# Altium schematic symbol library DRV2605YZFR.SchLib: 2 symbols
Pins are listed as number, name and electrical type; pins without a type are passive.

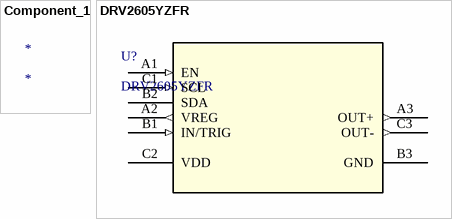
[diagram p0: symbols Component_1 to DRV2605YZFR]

## Component_1
designator *

## DRV2605YZFR
designator U?
No Description Available; Vendor: TEXAS INSTRUMENTS
footprint YZF9
pins: A1 EN (in), A2 VREG (out), A3 OUT+ (out), B1 IN/TRIG (in), B2 SDA, B3 GND (power), C1 SCL (in), C2 VDD (power), C3 OUT- (out)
